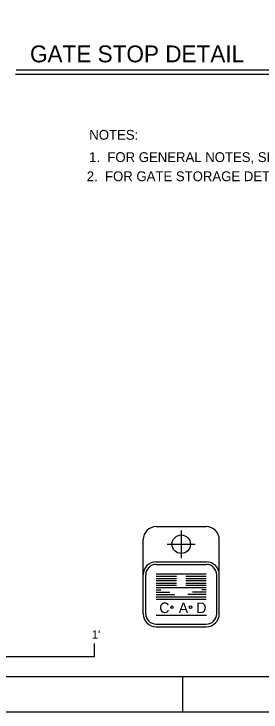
# Model space of a CAD drawing. Extents: x 0.1 to 13.5, y 0.1 to 9.5.
# Drawn here: x 9.949 to 11.122, y 0.125 to 3.44 of the extents above; entities that cross this region are included whole.
import ezdxf

# ---------------------------------------------------------------- set-up
doc = ezdxf.new("R2010")
doc.units = 0
for name, color, linetype in [('Level 1', 7, 'Continuous'), ('Level 25', 7, 'Continuous'), ('Level 3', 7, 'Continuous')]:
    doc.layers.add(name, color=color, linetype=linetype)

msp = doc.modelspace()

# ---------------------------------------------------------------- linework, layer by layer
at = {"layer": 'Level 1'}
for p, q in [((10.6241, 1.0053), (10.8623, 1.0053)), ((10.7432, 0.9877), (10.7432, 0.8557)), ((10.5625, 0.5916), (10.5625, 0.9437)), ((10.924, 0.5916), (10.924, 0.9437)), ((10.6772, 0.9217), (10.8092, 0.9217)), ((10.6241, 0.8381), (10.8623, 0.8381)), ((10.6241, 0.8258), (10.8623, 0.8258)), ((10.5748, 0.5916), (10.5748, 0.7765)), ((10.6241, 0.7818), (10.8623, 0.7818)), ((10.6241, 0.7708), (10.7212, 0.7708)), ((10.7652, 0.7708), (10.8623, 0.7708)), ((10.9116, 0.5916), (10.9116, 0.7765)), ((10.6241, 0.7598), (10.7212, 0.7598)), ((10.6241, 0.7488), (10.7212, 0.7488)), ((10.6241, 0.7377), (10.7212, 0.7377)), ((10.7652, 0.7598), (10.8623, 0.7598)), ((10.7652, 0.7488), (10.8623, 0.7488)), ((10.7652, 0.7377), (10.8623, 0.7377)), ((10.6241, 0.7267), (10.7212, 0.7267)), ((10.6241, 0.7157), (10.8623, 0.7157)), ((10.6241, 0.7047), (10.6461, 0.7047)), ((10.7652, 0.7267), (10.8623, 0.7267)), ((10.8623, 0.7047), (10.8403, 0.7047)), ((10.6241, 0.6937), (10.689, 0.6937)), ((10.6241, 0.6827), (10.7116, 0.6827)), ((10.6241, 0.6717), (10.8623, 0.6717)), ((10.8623, 0.6827), (10.7748, 0.6827)), ((10.8623, 0.6937), (10.7974, 0.6937)), ((10.6241, 0.6607), (10.8623, 0.6607)), ((10.6241, 0.5843), (10.8628, 0.5843)), ((10.6241, 0.5424), (10.8623, 0.5424)), ((10.6241, 0.5301), (10.8623, 0.5301)), ((10.3316, 0.3882), (10.3316, 0.4507)), ((8.3316, 0.3882), (10.3316, 0.3882)), ((10.75, 0.2917), (10.75, 0.125))]:
    msp.add_line(p, q, dxfattribs=at)
for points in [[(0.125, 9.4583), (13.4583, 9.4583), (13.4583, 0.125), (0.125, 0.125)], [(0.625, 9.2917), (13.2917, 9.2917), (13.2917, 0.2917), (0.625, 0.2917)]]:
    msp.add_lwpolyline(points, close=True, dxfattribs=at)
for centre, radius in [((10.7432, 0.9217), 0.044), ((10.6995, 0.6225), 0.00616), ((10.7878, 0.6226), 0.00616)]:
    msp.add_circle(centre, radius, dxfattribs=at)
for centre, radius, start, end in [((10.6241, 0.9437), 0.0616, 90, 180), ((10.8623, 0.9437), 0.0616, 0, 90), ((10.6241, 0.7765), 0.0616, 90, 180), ((10.8623, 0.7765), 0.0616, 0, 90), ((10.6241, 0.7765), 0.0493, 90, 180), ((10.8623, 0.7765), 0.0493, 0, 90), ((10.6241, 0.5917), 0.0616, 180, 270), ((10.6241, 0.5917), 0.0493, 180, 270), ((10.8623, 0.5917), 0.0616, 270, 360), ((10.8623, 0.5917), 0.0493, 270, 360)]:
    msp.add_arc(centre, radius, start, end, dxfattribs=at)
at = {"layer": 'Level 3'}
for p, q in [((9.9561, 3.1541), (11.2528, 3.1541)), ((9.9605, 3.175), (11.2661, 3.175))]:
    msp.add_line(p, q, dxfattribs=at)

# ---------------------------------------------------------------- texts
at = {"layer": 'Level 1'}
for s, height, p in [('C', 0.0501, (10.6391, 0.595)), ('A', 0.0501, (10.7312, 0.5946)), ('D', 0.0501, (10.8149, 0.595)), ("1'", 0.04, (10.319, 0.4731))]:
    msp.add_text(s, height=height, dxfattribs=at).set_placement(p)
at = {"layer": 'Level 25'}
for s, height, p in [('NOTES:', 0.04667, (10.307, 2.8424)), ('1.  FOR GENERAL NOTES, SEE DWG. 20.', 0.046667, (10.3058, 2.7365)), ('2.  FOR GATE STORAGE DETAILS, SEE DWG. 34.', 0.046667, (10.2948, 2.6457))]:
    msp.add_text(s, height=height, dxfattribs=at).set_placement(p)
at = {"layer": 'Level 3'}
msp.add_text('GATE STOP DETAIL', height=0.08, dxfattribs=at).set_placement((10.0254, 3.2101))

doc.saveas('drawing.dxf')
